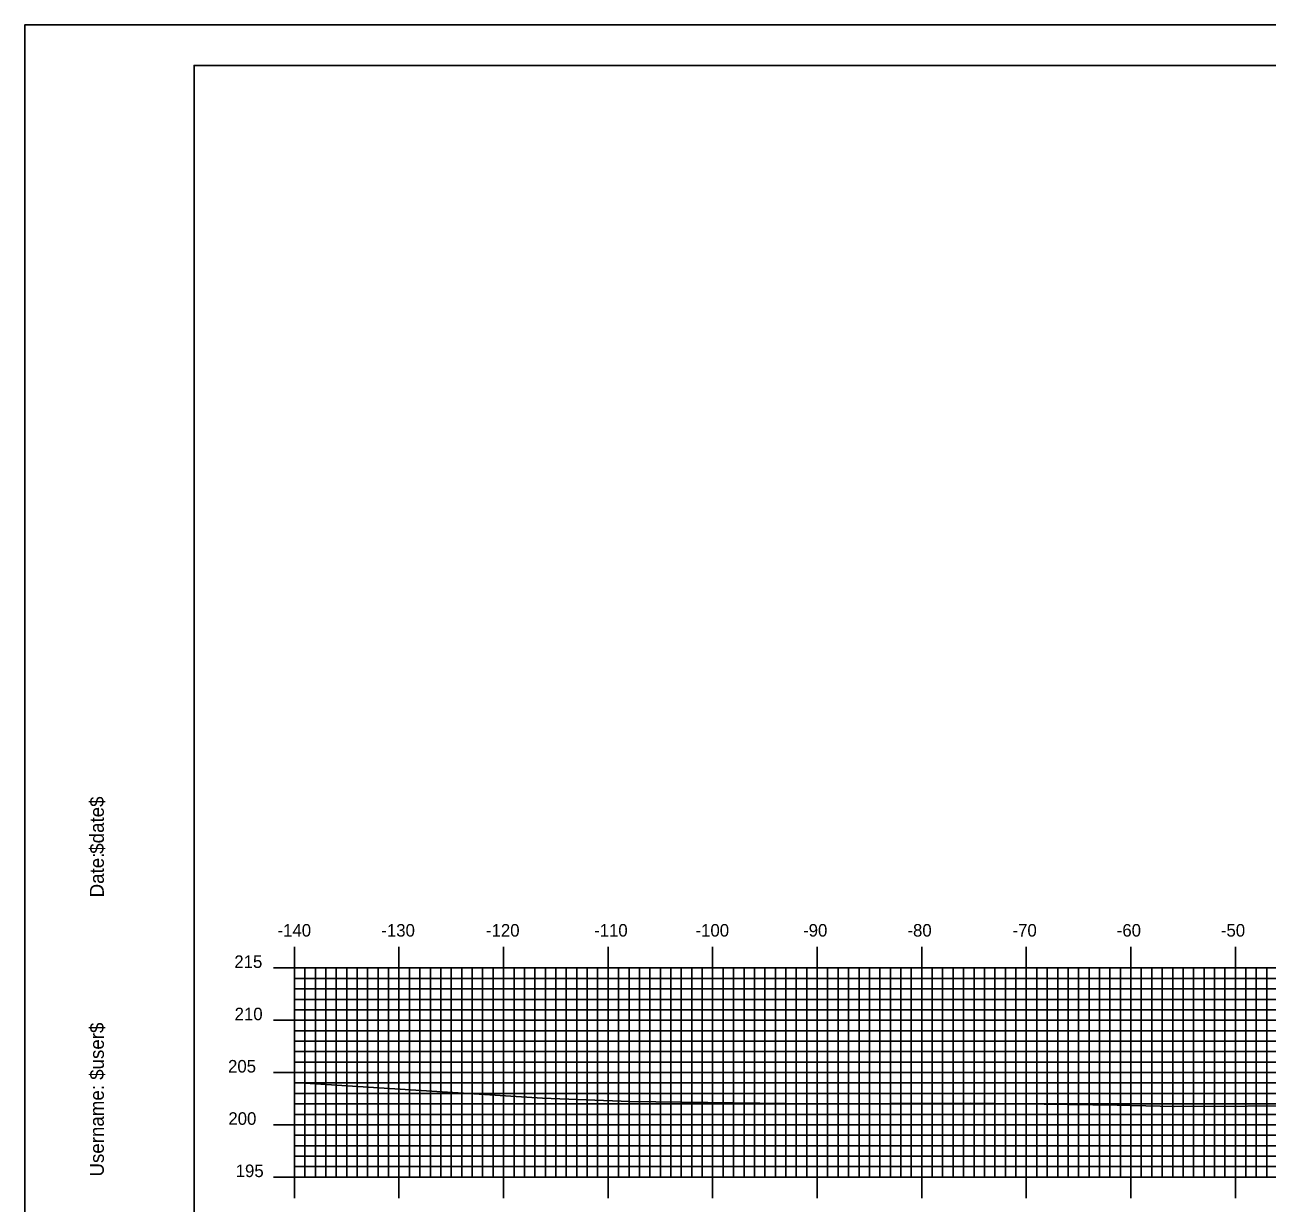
# Model space of a CAD drawing. Extents: x 852087 to 852430, y 366898 to 367118.
# Drawn here: x 852086.7 to 852205.6, y 367005.7 to 367118.4 of the extents above; entities that cross this region are included whole.
import ezdxf

# ---------------------------------------------------------------- set-up
doc = ezdxf.new("R2010")
doc.units = 0
for name, color, linetype in [('BORDER', 7, 'Continuous'), ('H_V ANNOTATION', 7, 'Continuous'), ('MAJOR', 7, 'Continuous'), ('MINOR', 7, 'Continuous'), ('PLOT BOUNDARY', 7, 'Continuous'), ('S_Roadway_Centerline', 7, 'Continuous')]:
    doc.layers.add(name, color=color, linetype=linetype)

msp = doc.modelspace()

# ---------------------------------------------------------------- linework, layer by layer
at = {"layer": 'BORDER'}
msp.add_lwpolyline([(852102.93, 366904.47), (852422.93, 366904.47), (852422.93, 367114.47), (852102.93, 367114.47)], close=True, dxfattribs=at)
at = {"layer": 'MAJOR'}
for p, q in [((852112.53, 367030.17), (852112.53, 367028.16)), ((852122.53, 367030.17), (852122.53, 367028.16)), ((852132.53, 367030.17), (852132.53, 367028.16)), ((852142.53, 367030.17), (852142.53, 367028.16)), ((852152.53, 367030.17), (852152.53, 367028.16)), ((852162.53, 367030.17), (852162.53, 367028.16)), ((852172.53, 367030.17), (852172.53, 367028.16)), ((852182.53, 367030.17), (852182.53, 367028.16)), ((852192.53, 367030.17), (852192.53, 367028.16)), ((852202.53, 367030.17), (852202.53, 367028.16)), ((852110.53, 367028.16), (852112.53, 367028.16)), ((852112.53, 367028.16), (852392.53, 367028.16)), ((852112.53, 367008.16), (852112.53, 367028.16)), ((852112.53, 367008.16), (852112.53, 367028.16)), ((852112.53, 367028.16), (852392.53, 367028.16)), ((852122.53, 367008.16), (852122.53, 367028.16)), ((852132.53, 367008.16), (852132.53, 367028.16)), ((852142.53, 367008.16), (852142.53, 367028.16)), ((852152.53, 367008.16), (852152.53, 367028.16)), ((852162.53, 367008.16), (852162.53, 367028.16)), ((852172.53, 367008.16), (852172.53, 367028.16)), ((852182.53, 367008.16), (852182.53, 367028.16)), ((852192.53, 367008.16), (852192.53, 367028.16)), ((852202.53, 367008.16), (852202.53, 367028.16)), ((852110.53, 367023.16), (852112.53, 367023.16)), ((852112.53, 367023.16), (852392.53, 367023.16)), ((852110.53, 367018.16), (852112.53, 367018.16)), ((852112.53, 367018.16), (852392.53, 367018.16)), ((852110.53, 367013.16), (852112.53, 367013.16)), ((852112.53, 367013.16), (852392.53, 367013.16)), ((852110.53, 367008.16), (852112.53, 367008.16)), ((852112.53, 367008.16), (852392.53, 367008.16)), ((852112.53, 367008.16), (852392.53, 367008.16)), ((852112.53, 367006.16), (852112.53, 367008.16)), ((852122.53, 367006.16), (852122.53, 367008.16)), ((852132.53, 367006.16), (852132.53, 367008.16)), ((852142.53, 367006.16), (852142.53, 367008.16)), ((852152.53, 367006.16), (852152.53, 367008.16)), ((852162.53, 367006.16), (852162.53, 367008.16)), ((852172.53, 367006.16), (852172.53, 367008.16)), ((852182.53, 367006.16), (852182.53, 367008.16)), ((852192.53, 367006.16), (852192.53, 367008.16)), ((852202.53, 367006.16), (852202.53, 367008.16))]:
    msp.add_line(p, q, dxfattribs=at)
at = {"layer": 'MINOR'}
for p, q in [((852113.53, 367008.16), (852113.53, 367028.16)), ((852114.53, 367008.16), (852114.53, 367028.16)), ((852115.53, 367008.16), (852115.53, 367028.16)), ((852116.53, 367008.16), (852116.53, 367028.16)), ((852117.53, 367008.16), (852117.53, 367028.16)), ((852118.53, 367008.16), (852118.53, 367028.16)), ((852119.53, 367008.16), (852119.53, 367028.16)), ((852120.53, 367008.16), (852120.53, 367028.16)), ((852121.53, 367008.16), (852121.53, 367028.16)), ((852123.53, 367008.16), (852123.53, 367028.16)), ((852124.53, 367008.16), (852124.53, 367028.16)), ((852125.53, 367008.16), (852125.53, 367028.16)), ((852126.53, 367008.16), (852126.53, 367028.16)), ((852127.53, 367008.16), (852127.53, 367028.16)), ((852128.53, 367008.16), (852128.53, 367028.16)), ((852129.53, 367008.16), (852129.53, 367028.16)), ((852130.53, 367008.16), (852130.53, 367028.16)), ((852131.53, 367008.16), (852131.53, 367028.16)), ((852133.53, 367008.16), (852133.53, 367028.16)), ((852134.53, 367008.16), (852134.53, 367028.16)), ((852135.53, 367008.16), (852135.53, 367028.16)), ((852136.53, 367008.16), (852136.53, 367028.16)), ((852137.53, 367008.16), (852137.53, 367028.16)), ((852138.53, 367008.16), (852138.53, 367028.16)), ((852139.53, 367008.16), (852139.53, 367028.16)), ((852140.53, 367008.16), (852140.53, 367028.16)), ((852141.53, 367008.16), (852141.53, 367028.16)), ((852143.53, 367008.16), (852143.53, 367028.16)), ((852144.53, 367008.16), (852144.53, 367028.16)), ((852145.53, 367008.16), (852145.53, 367028.16)), ((852146.53, 367008.16), (852146.53, 367028.16)), ((852147.53, 367008.16), (852147.53, 367028.16)), ((852148.53, 367008.16), (852148.53, 367028.16)), ((852149.53, 367008.16), (852149.53, 367028.16)), ((852150.53, 367008.16), (852150.53, 367028.16)), ((852151.53, 367008.16), (852151.53, 367028.16)), ((852153.53, 367008.16), (852153.53, 367028.16)), ((852154.53, 367008.16), (852154.53, 367028.16)), ((852155.53, 367008.16), (852155.53, 367028.16)), ((852156.53, 367008.16), (852156.53, 367028.16)), ((852157.53, 367008.16), (852157.53, 367028.16)), ((852158.53, 367008.16), (852158.53, 367028.16)), ((852159.53, 367008.16), (852159.53, 367028.16)), ((852160.53, 367008.16), (852160.53, 367028.16)), ((852161.53, 367008.16), (852161.53, 367028.16)), ((852163.53, 367008.16), (852163.53, 367028.16)), ((852164.53, 367008.16), (852164.53, 367028.16)), ((852165.53, 367008.16), (852165.53, 367028.16)), ((852166.53, 367008.16), (852166.53, 367028.16)), ((852167.53, 367008.16), (852167.53, 367028.16)), ((852168.53, 367008.16), (852168.53, 367028.16)), ((852169.53, 367008.16), (852169.53, 367028.16)), ((852170.53, 367008.16), (852170.53, 367028.16)), ((852171.53, 367008.16), (852171.53, 367028.16)), ((852173.53, 367008.16), (852173.53, 367028.16)), ((852174.53, 367008.16), (852174.53, 367028.16)), ((852175.53, 367008.16), (852175.53, 367028.16)), ((852176.53, 367008.16), (852176.53, 367028.16)), ((852177.53, 367008.16), (852177.53, 367028.16)), ((852178.53, 367008.16), (852178.53, 367028.16)), ((852179.53, 367008.16), (852179.53, 367028.16)), ((852180.53, 367008.16), (852180.53, 367028.16)), ((852181.53, 367008.16), (852181.53, 367028.16)), ((852183.53, 367008.16), (852183.53, 367028.16)), ((852184.53, 367008.16), (852184.53, 367028.16)), ((852185.53, 367008.16), (852185.53, 367028.16)), ((852186.53, 367008.16), (852186.53, 367028.16)), ((852187.53, 367008.16), (852187.53, 367028.16)), ((852188.53, 367008.16), (852188.53, 367028.16)), ((852189.53, 367008.16), (852189.53, 367028.16)), ((852190.53, 367008.16), (852190.53, 367028.16)), ((852191.53, 367008.16), (852191.53, 367028.16)), ((852193.53, 367008.16), (852193.53, 367028.16)), ((852194.53, 367008.16), (852194.53, 367028.16)), ((852195.53, 367008.16), (852195.53, 367028.16)), ((852196.53, 367008.16), (852196.53, 367028.16)), ((852197.53, 367008.16), (852197.53, 367028.16)), ((852198.53, 367008.16), (852198.53, 367028.16)), ((852199.53, 367008.16), (852199.53, 367028.16)), ((852200.53, 367008.16), (852200.53, 367028.16)), ((852201.53, 367008.16), (852201.53, 367028.16)), ((852203.53, 367008.16), (852203.53, 367028.16)), ((852204.53, 367008.16), (852204.53, 367028.16)), ((852205.53, 367008.16), (852205.53, 367028.16)), ((852112.53, 367027.16), (852392.53, 367027.16)), ((852112.53, 367027.16), (852114.54, 367027.16)), ((852112.53, 367026.16), (852392.53, 367026.16)), ((852112.53, 367026.16), (852114.54, 367026.16)), ((852112.53, 367025.16), (852392.53, 367025.16)), ((852112.53, 367025.16), (852114.54, 367025.16)), ((852112.53, 367024.16), (852392.53, 367024.16)), ((852112.53, 367024.16), (852114.54, 367024.16)), ((852112.53, 367022.16), (852392.53, 367022.16)), ((852112.53, 367022.16), (852114.54, 367022.16)), ((852112.53, 367021.16), (852392.53, 367021.16)), ((852112.53, 367021.16), (852114.54, 367021.16)), ((852112.53, 367020.16), (852392.53, 367020.16)), ((852112.53, 367020.16), (852114.54, 367020.16)), ((852112.53, 367019.16), (852392.53, 367019.16)), ((852112.53, 367019.16), (852114.54, 367019.16)), ((852112.53, 367017.16), (852392.53, 367017.16)), ((852112.53, 367017.16), (852114.54, 367017.16)), ((852112.53, 367016.16), (852392.53, 367016.16)), ((852112.53, 367016.16), (852114.54, 367016.16)), ((852112.53, 367015.16), (852392.53, 367015.16)), ((852112.53, 367015.16), (852114.54, 367015.16)), ((852112.53, 367014.16), (852392.53, 367014.16)), ((852112.53, 367014.16), (852114.54, 367014.16)), ((852112.53, 367012.16), (852392.53, 367012.16)), ((852112.53, 367012.16), (852114.54, 367012.16)), ((852112.53, 367011.16), (852392.53, 367011.16)), ((852112.53, 367011.16), (852114.54, 367011.16)), ((852112.53, 367010.16), (852392.53, 367010.16)), ((852112.53, 367010.16), (852114.54, 367010.16)), ((852112.53, 367009.16), (852392.53, 367009.16)), ((852112.53, 367009.16), (852114.54, 367009.16))]:
    msp.add_line(p, q, dxfattribs=at)
at = {"layer": 'PLOT BOUNDARY'}
msp.add_lwpolyline([(852086.74, 366898.35), (852426.74, 366898.35), (852426.74, 367118.35), (852086.74, 367118.35)], close=True, dxfattribs=at)
at = {"layer": 'S_Roadway_Centerline'}
msp.add_lwpolyline([(852112.53, 367017.2), (852136.25, 367015.7), (852144.61, 367015.39), (852159.52, 367015.2), (852160.44, 367015.18), (852169.5, 367015.19), (852177.21, 367015.22), (852191.22, 367015.05), (852196.71, 367014.91), (852210.64, 367014.98)], dxfattribs=at)

# ---------------------------------------------------------------- texts
at = {"layer": 'BORDER'}
for s, p in [('$date$', (852094.3, 367039.08)), ('Date:', (852094.3, 367034.91)), ('$user$', (852094.3, 367017.46)), ('Username:', (852094.3, 367008.21))]:
    msp.add_text(s, height=1.339, rotation=90, dxfattribs=at).set_placement(p)
at = {"layer": 'H_V ANNOTATION'}
for s, p in [('-140', (852110.91, 367031.16)), ('-130', (852120.84, 367031.16)), ('-120', (852130.85, 367031.16)), ('-110', (852141.19, 367031.16)), ('-100', (852150.89, 367031.16)), ('-90', (852161.18, 367031.16)), ('-80', (852171.16, 367031.16)), ('-70', (852181.21, 367031.16)), ('-60', (852191.18, 367031.16)), ('-50', (852201.14, 367031.16)), ('215', (852106.78, 367028.16)), ('210', (852106.81, 367023.16)), ('205', (852106.18, 367018.16)), ('200', (852106.21, 367013.16)), ('195', (852106.91, 367008.16))]:
    msp.add_text(s, height=1.2, dxfattribs=at).set_placement(p)
at = {"layer": 'MAJOR'}
msp.add_text('-', height=0.012, dxfattribs=at).set_placement((852112.52, 367008.16))

doc.saveas('drawing.dxf')
